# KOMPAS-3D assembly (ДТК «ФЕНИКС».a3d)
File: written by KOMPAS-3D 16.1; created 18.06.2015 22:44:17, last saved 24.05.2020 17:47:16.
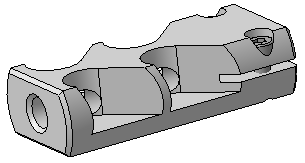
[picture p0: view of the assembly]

Referenced files in D:\Новая папка\работа\Чертежи\Компенсатор\ДТК «ФЕНИКС»\: ДТК «ФЕНИКС».m3d
Referenced files in C:\Program Files\ASCON\KOMPAS-3D V16\Libs\PartLib\DATA\VAULT\Methods\kompas\3d\: PLib_Screw_ISO_1100.m3d
Referenced files: GRAPHIC.TDP
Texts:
  Zebra 000
  (ф) Zebra 000 ТДК "Феникс"
  Hexagon socket head cap screw ISO 4762 - М4 x 6 - 10.9
  head2
  fillet10
  head4
  fillet13
  head8
  fillet6
  fillet4
  head7
  fillet5
  fillet7
  head6
  head3
  head5
  fillet1
  fillet11
  head11
  fillet9
  fillet8
  fillet12
  head10
  groove5
  head1
  fillet3
  Hexagon socket head cap screw ISO 4762-М4 x 6-10.9
  (-) Hexagon socket head cap screw ISO 4762 - М4 x 6 - 10.9 (1)
  (-) Hexagon socket head cap screw ISO 4762 - М4 x 6 - 10.9 (2)
  Hexagon socket head cap screw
